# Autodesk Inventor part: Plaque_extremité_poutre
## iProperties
Shininess: 64.0
Length Units: 11269
Angle Units: 11279
Time Units: 11290
Mass Units: 11283
Length Display Precision: 3
Angle Display Precision: 2
Compacted: True
Part Number: Plaque_extremité_poutre
Document SubType Name: Modeling
Created: 2008-04
Material: Par défaut
Designer: Pascal
Density: 0.0
Volumn: 0.0
Area: 0.0
PropertySet Name: Model Information
Control State: 0
Master: False
Checked Out: False
DESIGNATION: pièce
Author: Pascal
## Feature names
1. Extrusion1
2. Extrusion2
